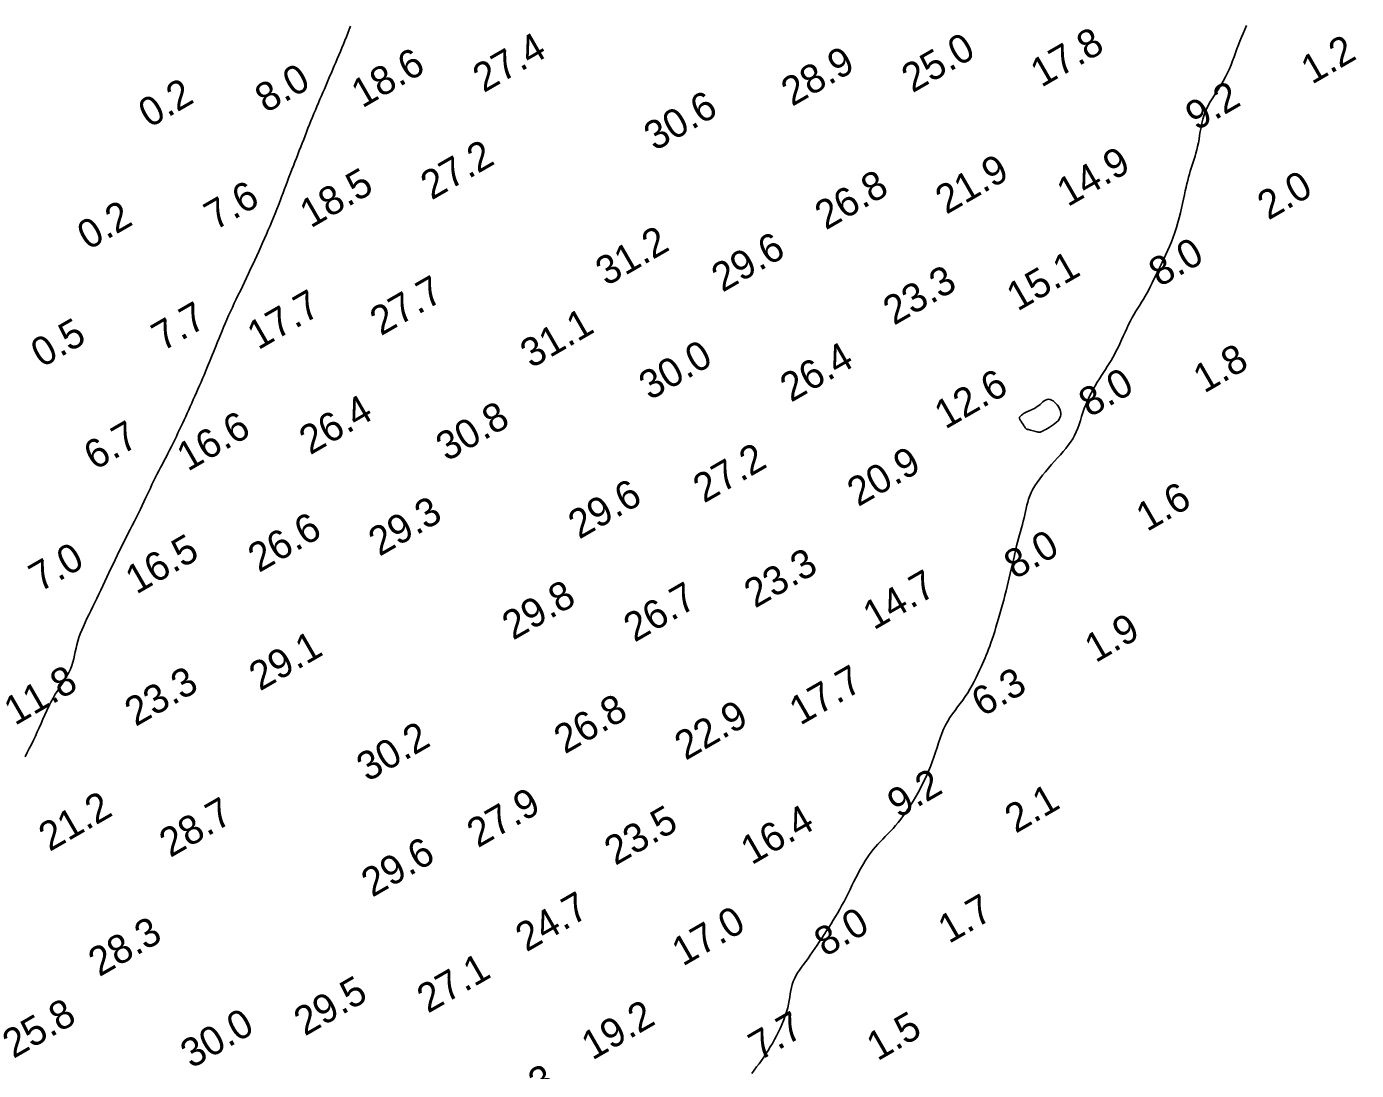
# Model space of a CAD drawing. Extents: x 3024098 to 3056816, y 418252 to 509144.
# Drawn here: x 3028305.6 to 3028537.3, y 425476.1 to 425657.9 of the extents above; entities that cross this region are included whole.
import ezdxf

# ---------------------------------------------------------------- set-up
doc = ezdxf.new("R2010")
doc.units = 0
doc.layers.add('V-CHAN-CONT-EL10', color=7, linetype='Continuous')
doc.layers.add('V-TOPO-SOUN-0911', color=7, linetype='Continuous')

msp = doc.modelspace()

# ---------------------------------------------------------------- linework, layer by layer
at = {"layer": 'V-CHAN-CONT-EL10'}
for points in [[(3028305.35, 425530.77), (3028305.72, 425531.48), (3028306.08, 425532.19), (3028306.44, 425532.91), (3028306.79, 425533.63), (3028307.13, 425534.35), (3028307.47, 425535.09), (3028307.8, 425535.83), (3028308.12, 425536.58), (3028308.45, 425537.34), (3028308.78, 425538.08), (3028309.11, 425538.83), (3028309.46, 425539.56), (3028309.82, 425540.28), (3028310.21, 425540.98), (3028310.61, 425541.67), (3028311.02, 425542.33), (3028311.44, 425542.98), (3028311.85, 425543.61), (3028312.24, 425544.23), (3028312.61, 425544.84), (3028312.94, 425545.45), (3028313.23, 425546.05), (3028313.47, 425546.65), (3028313.66, 425547.25), (3028313.82, 425547.85), (3028313.96, 425548.45), (3028314.09, 425549.05), (3028314.22, 425549.66), (3028314.36, 425550.28), (3028314.53, 425550.9), (3028314.73, 425551.53), (3028314.96, 425552.17), (3028315.21, 425552.82), (3028315.5, 425553.48), (3028315.79, 425554.15), (3028316.11, 425554.83), (3028316.44, 425555.51), (3028316.78, 425556.21), (3028317.12, 425556.91), (3028317.47, 425557.62), (3028317.82, 425558.34), (3028318.18, 425559.07), (3028318.53, 425559.8), (3028318.89, 425560.54), (3028319.25, 425561.28), (3028319.6, 425562.03), (3028319.96, 425562.78), (3028320.31, 425563.53), (3028320.67, 425564.29), (3028321.02, 425565.05), (3028321.38, 425565.8), (3028321.75, 425566.56), (3028322.12, 425567.32), (3028322.49, 425568.08), (3028322.87, 425568.84), (3028323.25, 425569.59), (3028323.64, 425570.34), (3028324.02, 425571.07), (3028324.4, 425571.8), (3028324.76, 425572.51), (3028325.11, 425573.2), (3028325.44, 425573.88), (3028325.76, 425574.53), (3028326.06, 425575.16), (3028326.34, 425575.78), (3028326.62, 425576.38), (3028326.89, 425576.98), (3028327.17, 425577.57), (3028327.44, 425578.16), (3028327.73, 425578.75), (3028328.02, 425579.34), (3028328.32, 425579.94), (3028328.63, 425580.54), (3028328.95, 425581.14), (3028329.27, 425581.75), (3028329.58, 425582.36), (3028329.9, 425582.96), (3028330.21, 425583.57), (3028330.52, 425584.17), (3028330.83, 425584.78), (3028331.12, 425585.38), (3028331.41, 425585.98), (3028331.7, 425586.57), (3028331.98, 425587.17), (3028332.26, 425587.75), (3028332.54, 425588.34), (3028332.81, 425588.91), (3028333.08, 425589.48), (3028333.34, 425590.06), (3028333.6, 425590.63), (3028333.87, 425591.2), (3028334.13, 425591.78), (3028334.4, 425592.37), (3028334.66, 425592.97), (3028334.93, 425593.57), (3028335.2, 425594.19), (3028335.47, 425594.8), (3028335.74, 425595.42), (3028336, 425596.04), (3028336.26, 425596.66), (3028336.52, 425597.26), (3028336.77, 425597.86), (3028337.02, 425598.44), (3028337.25, 425599.01), (3028337.49, 425599.57), (3028337.72, 425600.13), (3028337.95, 425600.7), (3028338.18, 425601.26), (3028338.42, 425601.84), (3028338.65, 425602.42), (3028338.9, 425603.03), (3028339.14, 425603.65), (3028339.4, 425604.28), (3028339.66, 425604.93), (3028339.93, 425605.59), (3028340.21, 425606.26), (3028340.51, 425606.94), (3028340.81, 425607.63), (3028341.13, 425608.33), (3028341.46, 425609.04), (3028341.8, 425609.76), (3028342.15, 425610.48), (3028342.5, 425611.21), (3028342.86, 425611.95), (3028343.22, 425612.69), (3028343.58, 425613.45), (3028343.94, 425614.2), (3028344.3, 425614.97), (3028344.65, 425615.73), (3028345.01, 425616.5), (3028345.36, 425617.27), (3028345.71, 425618.04), (3028346.06, 425618.8), (3028346.4, 425619.56), (3028346.74, 425620.31), (3028347.07, 425621.05), (3028347.4, 425621.79), (3028347.72, 425622.53), (3028348.04, 425623.26), (3028348.35, 425623.98), (3028348.65, 425624.7), (3028348.94, 425625.42), (3028349.23, 425626.14), (3028349.5, 425626.85), (3028349.77, 425627.57), (3028350.04, 425628.27), (3028350.29, 425628.98), (3028350.55, 425629.67), (3028350.81, 425630.36), (3028351.07, 425631.05), (3028351.32, 425631.73), (3028351.58, 425632.4), (3028351.84, 425633.06), (3028352.1, 425633.72), (3028352.36, 425634.38), (3028352.62, 425635.03), (3028352.88, 425635.69), (3028353.13, 425636.34), (3028353.39, 425636.99), (3028353.64, 425637.64), (3028353.89, 425638.29), (3028354.14, 425638.93), (3028354.39, 425639.58), (3028354.64, 425640.23), (3028354.9, 425640.87), (3028355.15, 425641.51), (3028355.42, 425642.15), (3028355.68, 425642.79), (3028355.94, 425643.42), (3028356.21, 425644.05), (3028356.47, 425644.67), (3028356.73, 425645.28), (3028356.99, 425645.89), (3028357.25, 425646.48), (3028357.5, 425647.06), (3028357.74, 425647.64), (3028357.98, 425648.21), (3028358.23, 425648.78), (3028358.47, 425649.35), (3028358.72, 425649.92), (3028358.97, 425650.51), (3028359.22, 425651.11), (3028359.48, 425651.72), (3028359.75, 425652.35), (3028360.02, 425652.98), (3028360.29, 425653.62), (3028360.56, 425654.27), (3028360.82, 425654.91), (3028361.09, 425655.55), (3028361.34, 425656.18), (3028361.59, 425656.81), (3028361.82, 425657.43), (3028362.06, 425658.04)], [(3028518.19, 425658.11), (3028517.89, 425657.44), (3028517.6, 425656.77), (3028517.31, 425656.1), (3028517.03, 425655.42), (3028516.77, 425654.75), (3028516.52, 425654.07), (3028516.27, 425653.39), (3028516.03, 425652.7), (3028515.78, 425652.01), (3028515.52, 425651.31), (3028515.23, 425650.61), (3028514.91, 425649.9), (3028514.55, 425649.19), (3028514.14, 425648.47), (3028513.7, 425647.75), (3028513.24, 425647.02), (3028512.77, 425646.29), (3028512.31, 425645.55), (3028511.87, 425644.82), (3028511.47, 425644.08), (3028511.12, 425643.33), (3028510.84, 425642.59), (3028510.61, 425641.85), (3028510.42, 425641.11), (3028510.27, 425640.39), (3028510.14, 425639.68), (3028510.03, 425638.99), (3028509.92, 425638.32), (3028509.81, 425637.68), (3028509.68, 425637.07), (3028509.54, 425636.48), (3028509.38, 425635.92), (3028509.22, 425635.38), (3028509.06, 425634.85), (3028508.89, 425634.32), (3028508.72, 425633.81), (3028508.56, 425633.29), (3028508.4, 425632.78), (3028508.25, 425632.25), (3028508.1, 425631.72), (3028507.96, 425631.16), (3028507.81, 425630.58), (3028507.67, 425629.96), (3028507.52, 425629.32), (3028507.36, 425628.63), (3028507.2, 425627.9), (3028507.04, 425627.12), (3028506.86, 425626.32), (3028506.67, 425625.5), (3028506.46, 425624.65), (3028506.23, 425623.8), (3028505.98, 425622.95), (3028505.71, 425622.11), (3028505.42, 425621.28), (3028505.1, 425620.46), (3028504.77, 425619.66), (3028504.42, 425618.88), (3028504.07, 425618.12), (3028503.72, 425617.37), (3028503.37, 425616.64), (3028503.03, 425615.94), (3028502.7, 425615.25), (3028502.38, 425614.59), (3028502.07, 425613.94), (3028501.76, 425613.32), (3028501.46, 425612.71), (3028501.16, 425612.12), (3028500.86, 425611.55), (3028500.55, 425611), (3028500.23, 425610.47), (3028499.91, 425609.95), (3028499.59, 425609.43), (3028499.26, 425608.91), (3028498.93, 425608.38), (3028498.61, 425607.83), (3028498.28, 425607.27), (3028497.96, 425606.67), (3028497.65, 425606.05), (3028497.33, 425605.39), (3028497.02, 425604.73), (3028496.72, 425604.05), (3028496.42, 425603.38), (3028496.11, 425602.71), (3028495.81, 425602.07), (3028495.5, 425601.45), (3028495.2, 425600.86), (3028494.89, 425600.31), (3028494.58, 425599.78), (3028494.26, 425599.26), (3028493.93, 425598.74), (3028493.6, 425598.23), (3028493.26, 425597.7), (3028492.91, 425597.16), (3028492.55, 425596.59), (3028492.19, 425595.99), (3028491.82, 425595.38), (3028491.46, 425594.75), (3028491.12, 425594.1), (3028490.78, 425593.44), (3028490.47, 425592.77), (3028490.18, 425592.09), (3028489.92, 425591.4), (3028489.69, 425590.71), (3028489.46, 425590.02), (3028489.24, 425589.33), (3028489.02, 425588.66), (3028488.78, 425588), (3028488.52, 425587.36), (3028488.23, 425586.74), (3028487.9, 425586.15), (3028487.53, 425585.58), (3028487.13, 425585.02), (3028486.7, 425584.47), (3028486.24, 425583.92), (3028485.76, 425583.37), (3028485.26, 425582.81), (3028484.74, 425582.24), (3028484.21, 425581.65), (3028483.68, 425581.04), (3028483.15, 425580.42), (3028482.64, 425579.79), (3028482.16, 425579.17), (3028481.71, 425578.55), (3028481.3, 425577.94), (3028480.95, 425577.35), (3028480.65, 425576.77), (3028480.41, 425576.2), (3028480.22, 425575.65), (3028480.06, 425575.11), (3028479.92, 425574.57), (3028479.8, 425574.03), (3028479.68, 425573.49), (3028479.56, 425572.93), (3028479.43, 425572.37), (3028479.28, 425571.8), (3028479.13, 425571.21), (3028478.97, 425570.62), (3028478.8, 425570.01), (3028478.64, 425569.4), (3028478.47, 425568.77), (3028478.31, 425568.14), (3028478.14, 425567.5), (3028477.99, 425566.85), (3028477.83, 425566.19), (3028477.68, 425565.51), (3028477.52, 425564.83), (3028477.36, 425564.13), (3028477.2, 425563.42), (3028477.03, 425562.69), (3028476.85, 425561.94), (3028476.67, 425561.18), (3028476.48, 425560.42), (3028476.29, 425559.64), (3028476.08, 425558.85), (3028475.88, 425558.05), (3028475.66, 425557.26), (3028475.44, 425556.46), (3028475.22, 425555.66), (3028474.99, 425554.87), (3028474.76, 425554.1), (3028474.53, 425553.34), (3028474.31, 425552.6), (3028474.08, 425551.9), (3028473.86, 425551.24), (3028473.65, 425550.61), (3028473.45, 425550.03), (3028473.25, 425549.49), (3028473.05, 425548.98), (3028472.85, 425548.48), (3028472.64, 425547.98), (3028472.42, 425547.48), (3028472.19, 425546.96), (3028471.94, 425546.41), (3028471.67, 425545.82), (3028471.38, 425545.2), (3028471.07, 425544.56), (3028470.73, 425543.9), (3028470.38, 425543.23), (3028470, 425542.56), (3028469.61, 425541.9), (3028469.19, 425541.26), (3028468.76, 425540.64), (3028468.31, 425540.04), (3028467.85, 425539.44), (3028467.4, 425538.84), (3028466.96, 425538.23), (3028466.52, 425537.61), (3028466.12, 425536.96), (3028465.74, 425536.28), (3028465.4, 425535.55), (3028465.09, 425534.8), (3028464.8, 425534.01), (3028464.52, 425533.2), (3028464.26, 425532.37), (3028463.99, 425531.54), (3028463.72, 425530.7), (3028463.43, 425529.87), (3028463.12, 425529.05), (3028462.79, 425528.25), (3028462.44, 425527.45), (3028462.07, 425526.67), (3028461.69, 425525.91), (3028461.3, 425525.16), (3028460.9, 425524.43), (3028460.49, 425523.72), (3028460.08, 425523.03), (3028459.66, 425522.36), (3028459.23, 425521.71), (3028458.8, 425521.08), (3028458.37, 425520.48), (3028457.93, 425519.89), (3028457.48, 425519.34), (3028457.04, 425518.8), (3028456.59, 425518.29), (3028456.14, 425517.8), (3028455.69, 425517.33), (3028455.24, 425516.86), (3028454.8, 425516.41), (3028454.37, 425515.97), (3028453.95, 425515.52), (3028453.55, 425515.07), (3028453.16, 425514.61), (3028452.79, 425514.14), (3028452.44, 425513.66), (3028452.09, 425513.16), (3028451.75, 425512.64), (3028451.42, 425512.1), (3028451.09, 425511.53), (3028450.77, 425510.94), (3028450.44, 425510.32), (3028450.11, 425509.67), (3028449.78, 425509.01), (3028449.44, 425508.33), (3028449.11, 425507.64), (3028448.76, 425506.94), (3028448.41, 425506.25), (3028448.06, 425505.57), (3028447.69, 425504.9), (3028447.33, 425504.23), (3028446.95, 425503.58), (3028446.57, 425502.94), (3028446.18, 425502.3), (3028445.79, 425501.67), (3028445.4, 425501.04), (3028445, 425500.42), (3028444.6, 425499.79), (3028444.2, 425499.17), (3028443.79, 425498.56), (3028443.39, 425497.95), (3028442.99, 425497.35), (3028442.58, 425496.77), (3028442.18, 425496.2), (3028441.79, 425495.65), (3028441.39, 425495.11), (3028441.01, 425494.6), (3028440.64, 425494.09), (3028440.29, 425493.59), (3028439.96, 425493.1), (3028439.67, 425492.61), (3028439.41, 425492.11), (3028439.2, 425491.61), (3028439.03, 425491.09), (3028438.9, 425490.57), (3028438.79, 425490.03), (3028438.69, 425489.47), (3028438.6, 425488.89), (3028438.51, 425488.29), (3028438.39, 425487.67), (3028438.24, 425487.03), (3028438.05, 425486.36), (3028437.82, 425485.67), (3028437.56, 425484.97), (3028437.27, 425484.26), (3028436.96, 425483.55), (3028436.63, 425482.85), (3028436.28, 425482.16), (3028435.93, 425481.49), (3028435.57, 425480.84), (3028435.2, 425480.22), (3028434.83, 425479.61), (3028434.44, 425479.02), (3028434.06, 425478.44), (3028433.66, 425477.86), (3028433.25, 425477.3), (3028432.83, 425476.73), (3028432.4, 425476.17), (3028431.96, 425475.6)]]:
    msp.add_lwpolyline(points, dxfattribs=at)
msp.add_lwpolyline([(3028480.36, 425587.7), (3028480.56, 425587.64), (3028480.79, 425587.58), (3028481.02, 425587.52), (3028481.25, 425587.47), (3028481.48, 425587.41), (3028481.69, 425587.37), (3028481.86, 425587.33), (3028482.01, 425587.31), (3028482.13, 425587.3), (3028482.23, 425587.31), (3028482.34, 425587.34), (3028482.45, 425587.38), (3028482.58, 425587.45), (3028482.74, 425587.54), (3028482.94, 425587.66), (3028483.2, 425587.79), (3028483.49, 425587.96), (3028483.81, 425588.14), (3028484.15, 425588.34), (3028484.48, 425588.56), (3028484.8, 425588.79), (3028485.09, 425589.04), (3028485.35, 425589.29), (3028485.54, 425589.55), (3028485.69, 425589.81), (3028485.79, 425590.08), (3028485.83, 425590.35), (3028485.83, 425590.63), (3028485.79, 425590.92), (3028485.7, 425591.2), (3028485.57, 425591.49), (3028485.41, 425591.77), (3028485.21, 425592.05), (3028484.99, 425592.31), (3028484.74, 425592.55), (3028484.48, 425592.75), (3028484.22, 425592.9), (3028483.95, 425593), (3028483.69, 425593.03), (3028483.43, 425592.99), (3028483.18, 425592.9), (3028482.94, 425592.75), (3028482.7, 425592.57), (3028482.47, 425592.37), (3028482.23, 425592.15), (3028481.99, 425591.94), (3028481.74, 425591.75), (3028481.49, 425591.58), (3028481.23, 425591.43), (3028480.97, 425591.3), (3028480.72, 425591.19), (3028480.46, 425591.09), (3028480.23, 425590.99), (3028480, 425590.9), (3028479.79, 425590.8), (3028479.59, 425590.7), (3028479.42, 425590.6), (3028479.27, 425590.5), (3028479.13, 425590.39), (3028479.01, 425590.29), (3028478.91, 425590.2), (3028478.83, 425590.11), (3028478.76, 425590.03), (3028478.7, 425589.96), (3028478.66, 425589.91), (3028478.64, 425589.86), (3028478.62, 425589.82), (3028478.61, 425589.79), (3028478.61, 425589.76), (3028478.61, 425589.74), (3028478.61, 425589.72), (3028478.62, 425589.7), (3028478.62, 425589.68), (3028478.64, 425589.65), (3028478.65, 425589.61), (3028478.68, 425589.57), (3028478.72, 425589.5), (3028478.77, 425589.42), (3028478.83, 425589.32), (3028478.91, 425589.2), (3028479, 425589.05), (3028479.1, 425588.9), (3028479.2, 425588.74), (3028479.31, 425588.58), (3028479.4, 425588.42), (3028479.49, 425588.28), (3028479.57, 425588.16), (3028479.63, 425588.07), (3028479.69, 425587.99), (3028479.74, 425587.93), (3028479.79, 425587.89), (3028479.86, 425587.85), (3028479.94, 425587.82), (3028480.05, 425587.79), (3028480.19, 425587.75)], close=True, dxfattribs=at)

# ---------------------------------------------------------------- texts
at = {"layer": 'V-TOPO-SOUN-0911'}
for s, p in [('27.4 ', (3028385.27, 425646.35)), ('25.0 ', (3028459.99, 425646.32)), ('17.8 ', (3028482.45, 425647.27)), ('18.6 ', (3028364.1, 425643.67)), ('28.9 ', (3028439.01, 425643.96)), ('1.2', (3028529.59, 425647.8)), ('8.0', (3028347.32, 425642.81)), ('0.2', (3028327, 425640.22)), ('9.2', (3028509.45, 425639.73)), ('30.6 ', (3028415.09, 425636.19)), ('27.2 ', (3028376.18, 425627.65)), ('14.9 ', (3028487.04, 425626.47)), ('18.5 ', (3028355.11, 425622.76)), ('21.9 ', (3028465.88, 425625.16)), ('7.6', (3028338.45, 425622.38)), ('26.8 ', (3028444.88, 425622.43)), ('2.0', (3028522, 425624.15)), ('0.2', (3028316.34, 425618.93)), ('31.2 ', (3028406.66, 425612.66)), ('29.6 ', (3028426.87, 425611.58)), ('8.0', (3028503.06, 425612.5)), ('15.1 ', (3028478.29, 425608.28)), ('23.3 ', (3028456.76, 425605.83)), ('27.7 ', (3028367.35, 425604)), ('7.7', (3028329.3, 425601.31)), ('17.7 ', (3028345.96, 425601.54)), ('31.1 ', (3028393.55, 425598.34)), ('0.5', (3028308.26, 425598.46)), ('30.0 ', (3028414.22, 425592.77)), ('26.4 ', (3028438.81, 425592.42)), ('1.8', (3028510.82, 425594)), ('12.6 ', (3028465.71, 425587.73)), ('8.0', (3028490.86, 425589.8)), ('26.4 ', (3028355.02, 425583.26)), ('30.8 ', (3028378.84, 425582.11)), ('6.7', (3028317.48, 425580.58)), ('16.6 ', (3028333.69, 425580.38)), ('27.2 ', (3028423.65, 425574.86)), ('20.9 ', (3028450.52, 425574.24)), ('29.6 ', (3028401.9, 425568.57)), ('1.6', (3028500.85, 425569.89)), ('29.3 ', (3028367.09, 425565.58)), ('26.6 ', (3028346.09, 425562.76)), ('16.5 ', (3028324.73, 425558.98)), ('8.0', (3028477.84, 425561.58)), ('7.0', (3028307.92, 425559.38)), ('23.3 ', (3028432.54, 425556.56)), ('14.7 ', (3028453.25, 425552.75)), ('29.8 ', (3028390.38, 425550.98)), ('26.7 ', (3028411.55, 425550.62)), ('1.9', (3028491.89, 425547.05)), ('29.1 ', (3028346.27, 425542.13)), ('11.8 ', (3028303.57, 425536.12)), ('23.3 ', (3028324.6, 425535.95)), ('17.7 ', (3028440.42, 425536.15)), ('6.3', (3028472.18, 425537.63)), ('26.8 ', (3028399.41, 425531.16)), ('22.9 ', (3028420.44, 425530.05)), ('30.2 ', (3028365.02, 425526.31)), ('9.2', (3028457.51, 425519.98)), ('21.2 ', (3028309.61, 425514.17)), ('27.9 ', (3028384.25, 425514.82)), ('2.1', (3028477.96, 425517.34)), ('28.7 ', (3028330.64, 425513.12)), ('23.5 ', (3028408.19, 425511.74)), ('16.4 ', (3028431.95, 425511.84)), ('29.6 ', (3028365.84, 425506.2)), ('24.7 ', (3028392.71, 425496.68)), ('1.7', (3028466.34, 425498.13)), ('17.0 ', (3028419.96, 425494.19)), ('8.0', (3028444.76, 425495.83)), ('28.3 ', (3028318.27, 425492.35)), ('27.1 ', (3028375.54, 425486)), ('29.5 ', (3028354.09, 425482.02)), ('25.8 ', (3028303.31, 425478.11)), ('19.2 ', (3028404.2, 425477.82)), ('30.0 ', (3028334.33, 425476.37)), ('7.7', (3028433.33, 425477.72)), ('1.5', (3028453.89, 425477.69)), ('23.3 ', (3028386.91, 425466.69))]:
    msp.add_text(s, height=5, rotation=30, dxfattribs=at).set_placement(p)

doc.saveas('drawing.dxf')
